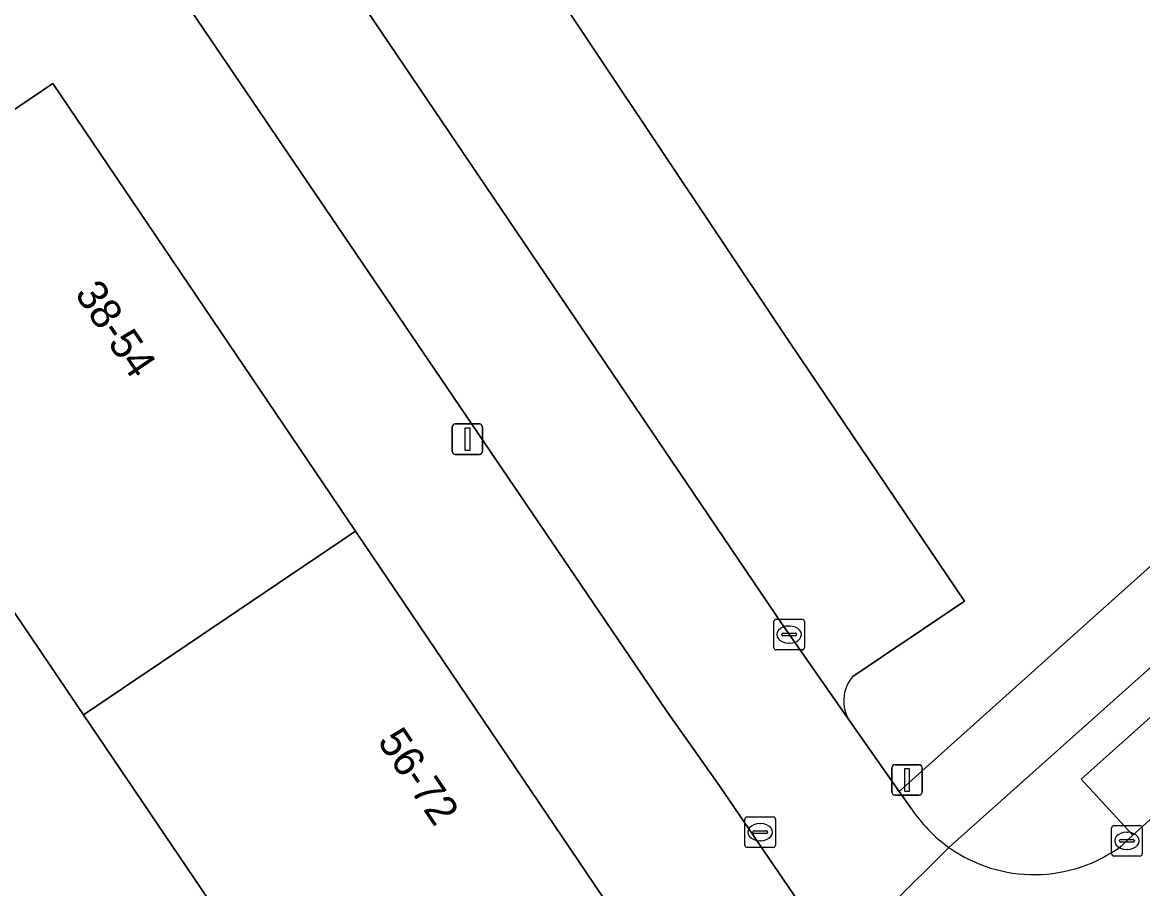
# Model space of a CAD drawing. Extents: x 157445 to 158888, y 383061 to 384688.
# Drawn here: x 157975.13 to 158011.77, y 383682.59 to 383710.94 of the extents above; entities that cross this region are included whole.
import ezdxf

# ---------------------------------------------------------------- set-up
doc = ezdxf.new("R2010")
doc.units = 0
for name, color, linetype in [('IMGEO_Erf', 7, 'Continuous'), ('IMGEO_Groenvoorziening', 7, 'Continuous'), ('IMGEO_Haag', 7, 'Continuous'), ('IMGEO_Kolk', 7, 'Continuous'), ('IMGEO_Lichtmast', 7, 'Continuous'), ('IMGEO_Pand', 7, 'Continuous'), ('IMGEO_Pand_nummerreeks', 7, 'Continuous'), ('IMGEO_Parkeervlak_open', 7, 'Continuous'), ('IMGEO_Rijbaan_lokaal_open', 7, 'Continuous'), ('IMGEO_Voetpad_open', 7, 'Continuous')]:
    doc.layers.add(name, color=color, linetype=linetype)

msp = doc.modelspace()

# ---------------------------------------------------------------- linework, layer by layer
at = {"layer": 'IMGEO_Erf'}
msp.add_lwpolyline([(157962.584, 383691.706), (157980.849, 383672.741), (157983.547, 383670.086), (157985.917, 383667.527), (157986.941, 383666.802), (158001.618, 383680.14), (158001.161, 383681.223), (157997.935, 383685.955), (157996.195, 383688.407), (157977.467, 383716.022)], dxfattribs=at)
msp.add_lwpolyline([(157976.118, 383708.944), (157986.024, 383694.295), (157995.93, 383679.646), (157987.035, 383673.631), (157977.129, 383688.281), (157967.224, 383702.93)], close=True, dxfattribs=at)
at = {"layer": 'IMGEO_Groenvoorziening'}
for points in [[(158001.273, 383731.275), (158003.717, 383727.607), (158000, 383725.104), (157994.325, 383721.207), (157989.557, 383717.95), (157990.089, 383717.121), (157989.426, 383716.622), (157991.886, 383712.972), (158000, 383700.807), (158005.947, 383692.006), (158002.291, 383689.538)], [(158002.195, 383688.07), (158003.812, 383685.776), (158009.938, 383691.267), (158028.734, 383708.116), (158030.901, 383710.235), (158029.032, 383712.108), (158026.44, 383714.76)], [(158032.619, 383708.216), (158031.821, 383709.312), (158030.901, 383710.235), (158028.734, 383708.116), (158009.938, 383691.267), (158003.812, 383685.776), (158004.21, 383685.21)], [(158005.436, 383683.944), (158032.619, 383708.216)]]:
    msp.add_lwpolyline(points, dxfattribs=at)
msp.add_lwpolyline([(158019.808, 383691.872), (158031.556, 383702.299), (158029.903, 383704.181), (158009.769, 383686.181), (158011.458, 383684.342)], close=True, dxfattribs=at)
for centre, radius, start, end in [((158003.215, 383688.74), 1.221, 139.2021, 213.3148), ((158008.253, 383687.899), 4.856, 213.625, 234.5358)]:
    msp.add_arc(centre, radius, start, end, dxfattribs=at)
at = {"layer": 'IMGEO_Haag'}
for points in [[(158032.619, 383708.216), (158031.821, 383709.312), (158030.901, 383710.235), (158028.734, 383708.116), (158009.938, 383691.267), (158003.812, 383685.776), (158004.21, 383685.21)], [(158005.436, 383683.944), (158032.619, 383708.216)]]:
    msp.add_lwpolyline(points, dxfattribs=at)
msp.add_arc((158008.253, 383687.899), 4.856, 213.625, 234.5358, dxfattribs=at)
at = {"layer": 'IMGEO_Kolk'}
for p, q in [((157999.709, 383690.481), (157999.709, 383691.333)), ((157999.784, 383691.407), (158000.636, 383691.407)), ((158000.197, 383691.187), (158000.222, 383691.187)), ((158000.71, 383691.333), (158000.71, 383690.481)), ((157999.968, 383690.901), (157999.968, 383690.913)), ((158000.406, 383690.864), (158000.008, 383690.864)), ((158000.011, 383690.95), (158000.409, 383690.95)), ((158000.452, 383690.913), (158000.452, 383690.901)), ((158000.22, 383690.627), (158000.195, 383690.627)), ((158000.636, 383690.407), (157999.784, 383690.407)), ((157998.837, 383684.942), (157999.689, 383684.942)), ((157998.762, 383684.016), (157998.762, 383684.868)), ((157999.25, 383684.722), (157999.275, 383684.722)), ((157999.763, 383684.868), (157999.763, 383684.016)), ((158010.761, 383683.732), (158010.761, 383684.584)), ((158010.836, 383684.658), (158011.688, 383684.658)), ((158011.762, 383684.584), (158011.762, 383683.732)), ((157999.021, 383684.436), (157999.021, 383684.448)), ((157999.459, 383684.399), (157999.061, 383684.399)), ((157999.064, 383684.485), (157999.462, 383684.485)), ((157999.505, 383684.448), (157999.505, 383684.436)), ((158011.063, 383684.201), (158011.461, 383684.201)), ((158011.249, 383684.438), (158011.274, 383684.438)), ((157999.689, 383683.942), (157998.837, 383683.942)), ((157999.273, 383684.162), (157999.248, 383684.162)), ((158011.02, 383684.152), (158011.02, 383684.164)), ((158011.458, 383684.115), (158011.06, 383684.115)), ((158011.272, 383683.878), (158011.247, 383683.878)), ((158011.504, 383684.164), (158011.504, 383684.152)), ((158011.688, 383683.658), (158010.836, 383683.658))]:
    msp.add_line(p, q, dxfattribs=at)
for points in [[(157999.709, 383690.481), (157999.709, 383691.333)], [(157999.784, 383691.407), (158000.636, 383691.407)], [(158000.71, 383691.333), (158000.71, 383690.481)], [(158000.636, 383690.407), (157999.784, 383690.407)], [(157998.837, 383684.942), (157999.689, 383684.942)], [(157998.762, 383684.016), (157998.762, 383684.868)], [(157999.763, 383684.868), (157999.763, 383684.016)], [(158010.761, 383683.732), (158010.761, 383684.584)], [(158010.836, 383684.658), (158011.688, 383684.658)], [(158011.762, 383684.584), (158011.762, 383683.732)], [(157999.689, 383683.942), (157998.837, 383683.942)], [(158011.688, 383683.658), (158010.836, 383683.658)]]:
    msp.add_lwpolyline(points, dxfattribs=at)
for centre, radius, start, end in [((157999.786, 383691.331), 0.0765, 91.552, 178.448), ((157999.786, 383691.331), 0.0765, 91.552, 178.448), ((158000.634, 383691.331), 0.0765, 1.552, 88.448), ((158000.634, 383691.331), 0.0765, 1.552, 88.448), ((158000.008, 383690.91), 0.0403, 85.8775, 175.7526), ((158000.005, 383690.9), 0.0366, 178.938, 274.7102), ((158000.409, 383690.907), 0.043, 264.8664, 352.4533), ((158000.413, 383690.912), 0.0386, 1.7309, 96.639), ((157999.786, 383690.483), 0.0765, 181.552, 268.448), ((157999.786, 383690.483), 0.0765, 181.552, 268.448), ((158000.634, 383690.483), 0.0765, 271.552, 358.448), ((158000.634, 383690.483), 0.0765, 271.552, 358.448), ((157998.839, 383684.866), 0.0765, 91.552, 178.448), ((157998.839, 383684.866), 0.0765, 91.552, 178.448), ((157999.687, 383684.866), 0.0765, 1.552, 88.448), ((157999.687, 383684.866), 0.0765, 1.552, 88.448), ((158010.838, 383684.582), 0.0765, 91.552, 178.448), ((158010.838, 383684.582), 0.0765, 91.552, 178.448), ((158011.686, 383684.582), 0.0765, 1.552, 88.448), ((158011.686, 383684.582), 0.0765, 1.552, 88.448), ((157999.061, 383684.445), 0.0403, 85.8775, 175.7526), ((157999.058, 383684.435), 0.0366, 178.938, 274.7102), ((157999.462, 383684.442), 0.043, 264.8664, 352.4533), ((157999.466, 383684.447), 0.0386, 1.7309, 96.639), ((158011.06, 383684.161), 0.0403, 85.8775, 175.7526), ((158011.465, 383684.163), 0.0386, 1.7309, 96.639), ((157998.839, 383684.018), 0.0765, 181.552, 268.448), ((157998.839, 383684.018), 0.0765, 181.552, 268.448), ((157999.687, 383684.018), 0.0765, 271.552, 358.448), ((157999.687, 383684.018), 0.0765, 271.552, 358.448), ((158011.057, 383684.151), 0.0366, 178.938, 274.7102), ((158011.461, 383684.158), 0.043, 264.8664, 352.4533), ((158010.838, 383683.734), 0.0765, 181.552, 268.448), ((158010.838, 383683.734), 0.0765, 181.552, 268.448), ((158011.686, 383683.734), 0.0765, 271.552, 358.448), ((158011.686, 383683.734), 0.0765, 271.552, 358.448)]:
    msp.add_arc(centre, radius, start, end, dxfattribs=at)
for centre, major_axis, ratio, start_param, end_param in [((158000.196, 383690.907), (-0.387, 0.002), 0.722429, 4.712389, 7.853982), ((158000.221, 383690.907), (-0.39, 0.002), 0.717154, 1.570796, 4.712389), ((157999.249, 383684.442), (-0.387, 0.002), 0.722429, 4.712389, 7.853982), ((157999.274, 383684.442), (-0.39, 0.002), 0.717154, 1.570796, 4.712389), ((158011.248, 383684.158), (-0.387, 0.002), 0.722429, 4.712389, 7.853982), ((158011.273, 383684.158), (-0.39, 0.002), 0.717154, 1.570796, 4.712389)]:
    msp.add_ellipse(centre, major_axis=major_axis, ratio=ratio, start_param=start_param, end_param=end_param, dxfattribs=at)
at = {"layer": 'IMGEO_Lichtmast'}
for p, q in [((157989.289, 383697.802), (157990.079, 383697.802)), ((157990.079, 383697.802), (157989.289, 383697.802)), ((157989.189, 383696.902), (157989.189, 383697.702)), ((157989.189, 383697.702), (157989.189, 383696.902)), ((157990.179, 383697.702), (157990.179, 383696.902)), ((157990.179, 383696.902), (157990.179, 383697.702)), ((157990.079, 383696.802), (157989.289, 383696.802)), ((157989.289, 383696.802), (157990.079, 383696.802)), ((158003.572, 383685.75), (158003.572, 383686.55)), ((158003.572, 383686.55), (158003.572, 383685.75)), ((158003.672, 383686.65), (158004.462, 383686.65)), ((158004.462, 383686.65), (158003.672, 383686.65)), ((158004.562, 383686.55), (158004.562, 383685.75)), ((158004.562, 383685.75), (158004.562, 383686.55)), ((158004.462, 383685.65), (158003.672, 383685.65)), ((158003.672, 383685.65), (158004.462, 383685.65))]:
    msp.add_line(p, q, dxfattribs=at)
for points in [[(157989.609, 383697.677), (157989.759, 383697.677), (157989.759, 383696.927), (157989.609, 383696.927), (157989.609, 383697.677)], [(158003.992, 383686.525), (158004.142, 383686.525), (158004.142, 383685.775), (158003.992, 383685.775), (158003.992, 383686.525)]]:
    msp.add_lwpolyline(points, dxfattribs=at)
for centre, start, end in [((157989.289, 383697.702), 90, 180), ((157989.289, 383697.702), 90, 180), ((157990.079, 383697.702), 0, 90), ((157990.079, 383697.702), 360, 90), ((157989.289, 383696.902), 180, 270), ((157989.289, 383696.902), 180, 270), ((157990.079, 383696.902), 270, 0), ((157990.079, 383696.902), 270, 0), ((158003.672, 383686.55), 90, 180), ((158003.672, 383686.55), 90, 180), ((158004.462, 383686.55), 0, 90), ((158004.462, 383686.55), 360, 90), ((158003.672, 383685.75), 180, 270), ((158003.672, 383685.75), 180, 270), ((158004.462, 383685.75), 270, 0), ((158004.462, 383685.75), 270, 0)]:
    msp.add_arc(centre, 0.1, start, end, dxfattribs=at)
at = {"layer": 'IMGEO_Pand'}
for points in [[(157977.129, 383688.281), (157986.024, 383694.295), (157976.118, 383708.944), (157967.224, 383702.93)], [(157977.129, 383688.281), (157987.035, 383673.631), (157995.93, 383679.646), (157986.024, 383694.295)]]:
    msp.add_lwpolyline(points, close=True, dxfattribs=at)
at = {"layer": 'IMGEO_Parkeervlak_open'}
for points in [[(158002.291, 383689.538), (158005.947, 383692.006), (158000, 383700.807), (157991.886, 383712.972), (157989.426, 383716.622), (157985.789, 383714.142)], [(157984.395, 383714.327), (157985.434, 383712.756), (158000, 383691.217), (158002.195, 383688.07)]]:
    msp.add_lwpolyline(points, dxfattribs=at)
msp.add_arc((158003.215, 383688.74), 1.221, 139.2021, 213.3148, dxfattribs=at)
at = {"layer": 'IMGEO_Rijbaan_lokaal_open'}
for points in [[(157977.467, 383716.022), (157996.195, 383688.407), (157997.935, 383685.955), (158001.161, 383681.223), (158001.618, 383680.14), (158005.436, 383683.944)], [(158004.21, 383685.21), (158003.812, 383685.776), (158002.195, 383688.07), (158000, 383691.217), (157985.434, 383712.756), (157984.395, 383714.327), (157983.293, 383716.032)], [(158031.556, 383702.299), (158019.808, 383691.872), (158011.458, 383684.342), (158011.095, 383684.001)], [(158005.436, 383683.944), (158001.618, 383680.14)]]:
    msp.add_lwpolyline(points, dxfattribs=at)
for centre, radius, start, end in [((158008.253, 383687.899), 4.856, 213.625, 234.5358), ((158008.226, 383687.871), 4.818, 234.6085, 306.5457)]:
    msp.add_arc(centre, radius, start, end, dxfattribs=at)
at = {"layer": 'IMGEO_Voetpad_open'}
for points in [[(158032.619, 383708.216), (158005.436, 383683.944)], [(158011.095, 383684.001), (158011.458, 383684.342), (158009.769, 383686.181), (158029.903, 383704.181), (158031.556, 383702.299)]]:
    msp.add_lwpolyline(points, dxfattribs=at)
msp.add_arc((158008.226, 383687.871), 4.818, 234.6085, 306.5457, dxfattribs=at)

# ---------------------------------------------------------------- texts
at = {"layer": 'IMGEO_Pand_nummerreeks'}
for s, p in [('38-54', (157976.816, 383702.057)), ('56-72', (157986.718, 383687.413))]:
    msp.add_text(s, height=1, rotation=304.0675, dxfattribs=at).set_placement(p)

doc.saveas('drawing.dxf')
